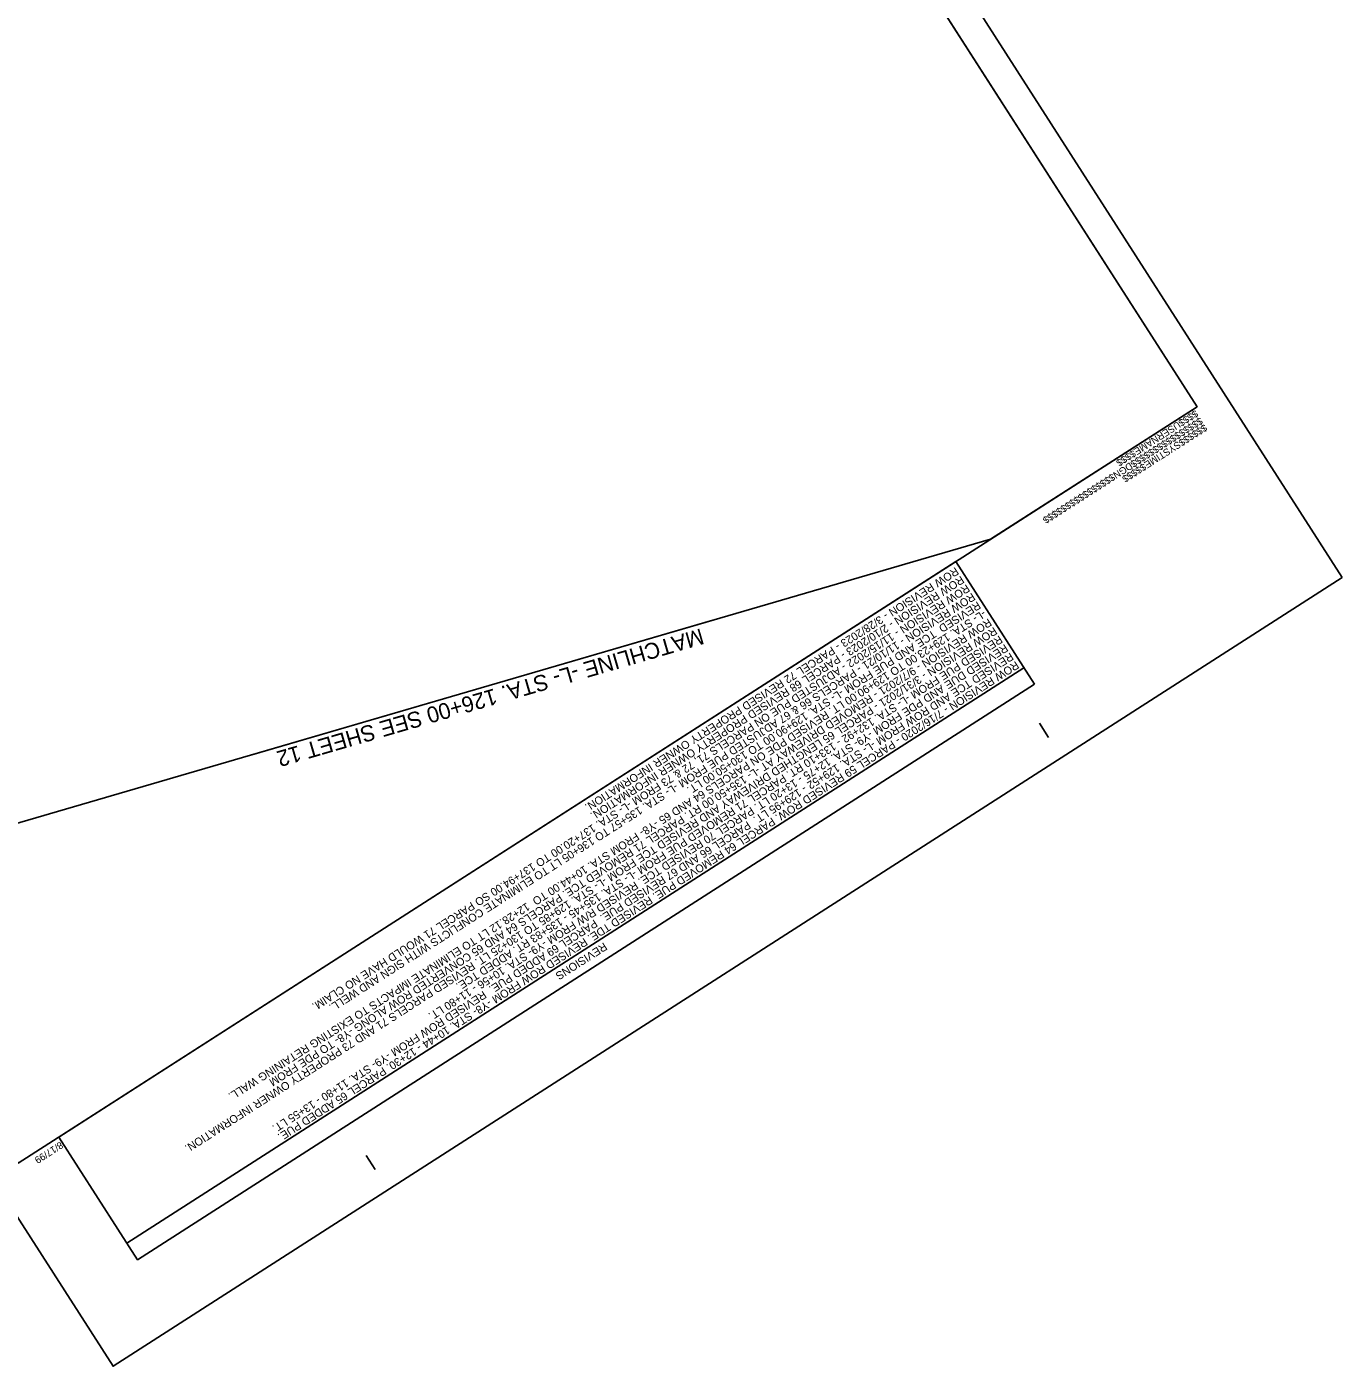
# Model space of a CAD drawing. Extents: x 476646 to 478477, y 498681 to 500689.
# Drawn here: x 477491 to 478477, y 498681 to 499685 of the extents above; entities that cross this region are included whole.
import ezdxf

# ---------------------------------------------------------------- set-up
doc = ezdxf.new("R2010")
doc.units = 0
for name, color, linetype in [('Matchline', 7, 'Continuous'), ('Matchline Text', 7, 'Continuous'), ('Sheet Block Revision CELL', 7, 'Continuous'), ('Sheet Clip Boundary CELL', 7, 'Continuous'), ('Sheet Plan CELL', 7, 'Continuous'), ('Sheet Plot Border Outside CELL', 7, 'Continuous')]:
    doc.layers.add(name, color=color, linetype=linetype)

msp = doc.modelspace()

# ---------------------------------------------------------------- linework, layer by layer
at = {"layer": 'Matchline'}
msp.add_line((478005.3, 499240.4), (477659.7, 499139.6), dxfattribs=at)
at = {"layer": 'Sheet Block Revision CELL'}
msp.add_line((478238.3, 499204.8), (477565.9, 498773.4), dxfattribs=at)
msp.add_lwpolyline([(478246.4, 499192.4), (477573.9, 498761), (477514.8, 498852.9), (478187.3, 499284.4)], close=True, dxfattribs=at)
at = {"layer": 'Sheet Clip Boundary CELL'}
msp.add_lwpolyline([(476918.3, 499916.9), (476844.5, 499831.1), (477346.7, 499048.4), (478213.4, 499301.1), (478368.3, 499400.5), (477650.4, 500519.4), (477583.1, 500476.2), (477579.2, 500482.2), (477490.9, 500619.8), (477447.8, 500592.1), (476917.4, 500038.8), (476928.6, 500021.4)], close=True, dxfattribs=at)
at = {"layer": 'Sheet Plan CELL'}
for p, q in [((478368.3, 499400.5), (478368.3, 499400.5)), ((478257, 499152.6), (478250.2, 499163.2)), ((477752, 498828.7), (477745.2, 498839.2))]:
    msp.add_line(p, q, dxfattribs=at)
msp.add_lwpolyline([(476674.5, 500096), (477484.5, 498833.5), (478368.3, 499400.5), (477558.3, 500663)], close=True, dxfattribs=at)
at = {"layer": 'Sheet Plot Border Outside CELL'}
msp.add_lwpolyline([(478477.1, 499272.5), (477568.1, 500689.5), (476646.4, 500098.2), (477555.5, 498681.2)], close=True, dxfattribs=at)

# ---------------------------------------------------------------- texts
at = {"layer": 'Matchline Text'}
msp.add_text('MATCHLINE -L- STA. 126+00 SEE SHEET 12', height=12, rotation=196.2011, dxfattribs=at).set_placement((477996.3, 499234.5))
at = {"layer": 'Sheet Block Revision CELL'}
for s, p in [('ROW REVISION - 3/28/2023 - PARCEL 72 REVISED PROPERTY OWNER INFORMATION. ', (478187.1, 499280.5)), ('ROW REVISION - 2/10/2023 - PARCEL 68 REVISED PROPERTY OWNER INFORMATION. ', (478191.2, 499274.1)), ('ROW REVISION - 11/15/2022 - ADJUSTED PUE ON PARCELS 71, 72 & 73 FROM -L- STA. 137+20.00 TO 137+94.00 SO PARCEL 71 WOULD HAVE NO CLAIM. ', (478195.4, 499267.7)), ('ROW REVISION - 11/10/21 - PARCELS 66 & 67 ADJUSTED PUE FROM -L- STA. 135+57 TO 136+05 LT TO ELIMINATE CONFLICTS WITH SIGN AND WELL. ', (478199.5, 499261.3)), ('REVISED  TCE AND PUE FROM -L- STA. 129+90.00 TO 130+50.00 LT. ', (478203.6, 499254.9)), ('-L- STA. 129+23.00 TO 129+90.00 LT. REVISED PDE ON PARCELS 64 AND 65 -Y8- FROM STA. 10+44.00 TO  12+28.12 LT TO ELIMINATE IMPACTS TO EXISTING RETAINING WALL. ', (478207.7, 499248.5)), ('ROW REVISION - 9/7/2021 - REMOVED DRIVEWAY AT -L- 135+50.00 RT. PARCEL 71 REMOVED TCE. PARCELS 64 AND 65 CONVERTED ROW ALONG -Y8- TO PDE FROM ', (478211.8, 499242.1)), ('ROW REVISION - 3/31/2021 - PARCEL 65 LENGTHED DRIVEWAY AND REVISED TCE FROM -L- STA. 129+85 TO 130+25 LT. REVISED PARCELS 71 AND 73 PROPERTY OWNER INFORMATION.', (478215.9, 499235.7)), ('REVISED DUE AND PDE FROM -Y9- STA. 12+75 - 13+20 LT. PARCEL 70 REVISED TCE. REVISED R/W FROM -Y9- STA. 10+56 - 11+80 LT. ', (478224.1, 499222.9)), ('REVISED PUE FROM -L- STA. 132+92 - 133+10 RT. PARCEL 71 REMOVED PUE FROM -L- STA. 135+45 - 135+83 RT. ADDED TCE. ', (478220, 499229.3)), ('REVISED TCE AND ROW FROM -L- STA. 129+52 - 129+95 LT.  PARCEL 66 AND 67 REVISED PUE.  PARCEL 69 ADDED PUE.  REVISED ROW FROM -Y9- STA. 11+80 - 13+55 LT.', (478228.2, 499216.5)), ('ROW REVISION - 7/16/2020 - PARCEL 59 REVISED ROW. PARCEL 64 REMOVED PUE. REVISED TDE. REVISED ROW FROM -Y8- STA. 10+44 - 12+30. PARCEL 65 ADDED PUE. ', (478232.3, 499210.1)), ('REVISIONS', (477923.5, 498999.1))]:
    msp.add_text(s, height=6, rotation=212.6818, dxfattribs=at).set_placement(p)
at = {"layer": 'Sheet Plan CELL'}
for s, p in [('$$$$$$$$$$$$$$$$DGN$$$$$$$$$$$$$$$$', (478370.4, 499392.8)), ('$$$$USERNAME$$$$', (478366.9, 499398.3)), ('$$$$$$SYSTIME$$$$$', (478373.7, 499387.7)), ('8/17/99', (477515.9, 498849.8))]:
    msp.add_text(s, height=5.25, rotation=212.6818, dxfattribs=at).set_placement(p)

doc.saveas('drawing.dxf')
